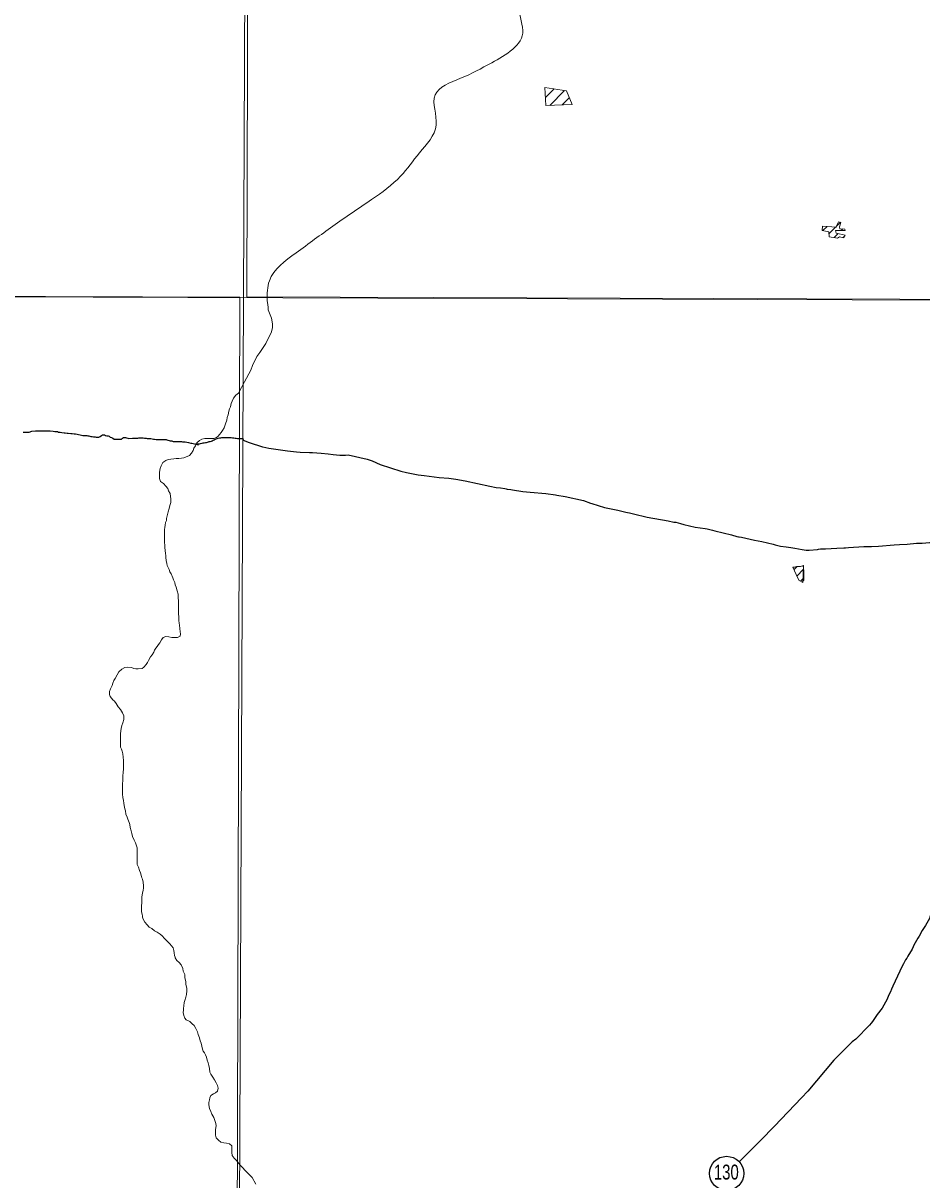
# Model space of a CAD drawing. Extents: x 553962 to 842807, y 8883888 to 9032388.
# Drawn here: x 595557 to 599781, y 8905786 to 8911220 of the extents above; entities that cross this region are included whole.
import ezdxf
from ezdxf.enums import TextEntityAlignment as Align

# ---------------------------------------------------------------- set-up
doc = ezdxf.new("R2010")
doc.units = 0
doc.header["$LTSCALE"] = 200
doc.layers.add('6', color=7, linetype='Continuous', lineweight=13)

msp = doc.modelspace()

# ---------------------------------------------------------------- linework, layer by layer
at = {"layer": '6'}
for p, q in [((598011.9, 8910870), (598052.8, 8910910.9)), ((598032.2, 8910833.7), (598101.8, 8910903.3)), ((598090.8, 8910835.7), (598123.8, 8910868.8)), ((599315.9, 8910245.3), (599335.8, 8910265.2)), ((599343.8, 8910230.8), (599375.6, 8910262.5)), ((599379.9, 8910266.9), (599397.8, 8910284.7)), ((599400.9, 8910245.4), (599408.4, 8910253)), ((599367.8, 8910212.3), (599386.4, 8910230.9)), ((599410.3, 8910212.4), (599419.1, 8910221.2)), ((574653.9, 8910009.3), (626625.7, 8909822.1)), ((599180, 8908652.7), (599194.5, 8908667.1)), ((599192.6, 8908622.8), (599224, 8908654.2)), ((599210.4, 8908598.2), (599221.5, 8908609.3))]:
    msp.add_line(p, q, dxfattribs=at)
at = {"layer": '6', "lineweight": 25}
msp.add_line((596590.3, 8909268.1), (596591.5, 8909261.3), dxfattribs=at)
at = {"layer": '6'}
for points in [[(596655.5, 8924715.8), (596593.3, 8909930.3), (596531.7, 8896026.7)], [(596627.8, 8909589.1), (596635.4, 8909611), (596655.3, 8909654), (596669.8, 8909672.5), (596698.4, 8909714.8), (596724.9, 8909769.1), (596729.8, 8909790.3), (596729.5, 8909807.5), (596724.5, 8909833.3), (596708.7, 8909872.6), (596708.4, 8909884.4), (596706.9, 8909897.8), (596703.8, 8909915.9)], [(596275.7, 8909174.6), (596288.2, 8909175.5), (596301.7, 8909176.9), (596311.7, 8909178.4), (596338.8, 8909188.3), (596347.8, 8909199.7), (596355.9, 8909212.7), (596359.4, 8909222.7), (596366.5, 8909233.7), (596373.6, 8909248.1), (596385.6, 8909259.1), (596397.7, 8909265.5), (596411.7, 8909268.9), (596453.7, 8909268.7), (596465.8, 8909273.5), (596474, 8909279.4), (596480.5, 8909287.6), (596487.5, 8909297.6), (596493.4, 8909307), (596502, 8909319.5), (596508.7, 8909337), (596514, 8909354.6), (596516.7, 8909367), (596520.3, 8909380.5), (596523.9, 8909397), (596527.4, 8909408), (596531, 8909417.9), (596535.1, 8909433.9), (596539.1, 8909443.9), (596545.7, 8909457.9), (596556.2, 8909471.9), (596569.8, 8909481.8), (596597.3, 8909535.3), (596627.8, 8909589.1)], [(596220.8, 8908789.1), (596221, 8908826.6), (596222.1, 8908840.6), (596223.1, 8908851.1), (596225.2, 8908861.6), (596226.2, 8908874.6), (596230.3, 8908884.1), (596230.8, 8908893.6), (596235.4, 8908912.1), (596239, 8908923.6), (596243, 8908940.1), (596246.6, 8908953.6), (596250.7, 8908967.6), (596250.8, 8908984.6), (596249.8, 8908995.6), (596247.4, 8909010.6), (596240.9, 8909023.6), (596237.5, 8909034.2), (596228.5, 8909045.2), (596217.1, 8909056.8), (596203.1, 8909066.9), (596197.7, 8909081.4), (596197.7, 8909093.9), (596198.3, 8909109.9), (596201.9, 8909127.4), (596205.9, 8909140.9), (596214, 8909155.9), (596227.1, 8909164.8), (596238.6, 8909169.8), (596251.6, 8909171.7), (596265.1, 8909172.6), (596275.7, 8909174.6)], [(595978.5, 8908119.2), (595983.6, 8908131.2), (595989.1, 8908141.2), (595998.7, 8908158.2), (596006.8, 8908172.2), (596020.8, 8908184.6), (596035.4, 8908193.5), (596045.9, 8908194), (596065.9, 8908192.4), (596076.9, 8908188.3), (596086.9, 8908186.8), (596097.9, 8908186.7), (596116.5, 8908188.6), (596125, 8908195.1), (596136.1, 8908207.5), (596141.1, 8908216), (596146.2, 8908226.5), (596156.2, 8908242.4), (596163.3, 8908252.9), (596170.8, 8908264.4), (596174.9, 8908274.4), (596180.9, 8908283.3), (596187, 8908291.3), (596194, 8908300.8), (596199.6, 8908309.3), (596207.2, 8908323.2), (596215.2, 8908333.7), (596227.7, 8908339.2), (596241.2, 8908336.6), (596255.7, 8908334.5), (596271.8, 8908333.4), (596283.3, 8908333.4), (596295.1, 8908339.9), (596297.3, 8908350.8), (596295.4, 8908360.8), (596293, 8908375.8), (596291.5, 8908391.9), (596290.6, 8908401.9), (596288.6, 8908413.9), (596288.2, 8908429.9), (596287.8, 8908446.9), (596288, 8908490.5), (596286.6, 8908508), (596286.1, 8908518), (596285.2, 8908537.5), (596281.3, 8908553.1), (596275.8, 8908571.1), (596272.4, 8908582.1), (596269.5, 8908592.7), (596263.5, 8908604.7), (596260, 8908614.2), (596252.6, 8908632.3), (596246.7, 8908642.8), (596243.2, 8908653.3), (596234.8, 8908671.4), (596232.8, 8908681.4), (596229.9, 8908695.4), (596228, 8908709), (596227, 8908719.5), (596226, 8908729), (596225.1, 8908743), (596223.7, 8908756), (596222.7, 8908768.5), (596221.8, 8908778.6), (596220.8, 8908789.1)], [(599174.8, 8908665), (599181.8, 8908664.8), (599191.6, 8908667.3), (599201.1, 8908666.7), (599210.7, 8908667.4), (599224.2, 8908672.1), (599225, 8908672.2), (599220.6, 8908592.6)], [(599220.6, 8908592.6), (599204.7, 8908601.3), (599197.1, 8908612.2), (599174.8, 8908665)], [(599224.2, 8908672.1), (599223.5, 8908670.4), (599225.7, 8908647.6), (599225.6, 8908640.5)], [(599225.6, 8908640.5), (599225.3, 8908603.8), (599222, 8908600), (599219.8, 8908595.6), (599220.6, 8908592.6)], [(596014.3, 8907828.6), (596014.4, 8907881.9), (596016.5, 8907895.9), (596018.1, 8907906.9), (596021.6, 8907919.9), (596026.2, 8907932.8), (596029.8, 8907948.8), (596029.8, 8907966.3), (596024.4, 8907980.4), (596014.5, 8907995), (596004, 8908008), (595994.1, 8908024.1), (595986.1, 8908034.1), (595979.2, 8908041.2), (595966.7, 8908056.8), (595963.3, 8908066.3), (595963.8, 8908080.8), (595967.9, 8908092.8), (595975, 8908108.8), (595978.5, 8908119.2)], [(596049.9, 8907479.9), (596046.2, 8907490.3), (596040.2, 8907503.9), (596038.8, 8907519.4), (596035.3, 8907529.4), (596031.9, 8907545.5), (596030.4, 8907555.5), (596029.5, 8907568.5), (596025.6, 8907582), (596024.6, 8907598.1), (596024.9, 8907649.1), (596025.4, 8907658.6), (596026, 8907674.1), (596026.5, 8907683.6), (596027.6, 8907700.1), (596029.2, 8907716.6), (596029.4, 8907756.2), (596027.9, 8907771.7), (596025, 8907786.7), (596022.6, 8907799.7), (596019.1, 8907808.8), (596014.2, 8907819.3), (596014.3, 8907828.6)], [(596115.7, 8907204.3), (596113.9, 8907210.7), (596108, 8907227.8), (596104.5, 8907239.3), (596099.1, 8907254.8), (596093.7, 8907267.4), (596092.7, 8907279.4), (596093, 8907346), (596090.6, 8907355.5), (596085.1, 8907369.5), (596078.2, 8907382.1), (596070.8, 8907398.6), (596067.8, 8907413.7), (596065.4, 8907425.2), (596059.4, 8907441.7), (596058, 8907454.7), (596055, 8907464.3), (596049.9, 8907479.9)], [(596117.5, 8907024.2), (596116.1, 8907034), (596114.2, 8907044.6), (596114.5, 8907115.1), (596118.1, 8907133.1), (596120.6, 8907146.6), (596123.2, 8907157.1), (596123.2, 8907168.1), (596121.3, 8907184.2), (596117.4, 8907198.2), (596115.7, 8907204.3)], [(596271.3, 8906832.7), (596268.8, 8906840.6), (596267.4, 8906852.6), (596266, 8906863.6), (596262.5, 8906875.6), (596254.5, 8906886.2), (596246.1, 8906895.2), (596235.1, 8906906.3), (596222.2, 8906920.4), (596211.2, 8906932.4), (596201.2, 8906941), (596187.3, 8906949.1), (596175.3, 8906955.7), (596161.8, 8906966.2), (596149.8, 8906973.8), (596139.9, 8906984.4), (596128.4, 8906996.9), (596121.5, 8907010), (596118, 8907020.5), (596117.5, 8907024.2)], [(596279.7, 8906817), (596272.3, 8906829.5), (596271.3, 8906832.7)], [(596461.2, 8906005.4), (596461.2, 8906022.7), (596463.8, 8906039.2), (596463.4, 8906051.2), (596457.4, 8906065.3), (596453.5, 8906078.3), (596444.6, 8906095.4), (596439.1, 8906106.9), (596433.7, 8906120.9), (596429.8, 8906138.5), (596429.8, 8906149), (596432.9, 8906162), (596433.9, 8906171.5), (596439.5, 8906182), (596451, 8906189.9), (596461, 8906195.4), (596470.1, 8906202.3), (596474.2, 8906216.8), (596471.2, 8906229.4), (596464.2, 8906241.4), (596455.8, 8906256), (596447.9, 8906268), (596439.9, 8906282.6), (596434.5, 8906292.6), (596433, 8906308.7), (596429.1, 8906323.7), (596426.2, 8906335.2), (596422.7, 8906348.8), (596419.3, 8906361.8), (596413.8, 8906373.3), (596408.8, 8906382.4), (596403.4, 8906390.9), (596399.9, 8906400.4), (596397, 8906413.4), (596393.6, 8906429), (596389.6, 8906440), (596386.2, 8906452.6), (596379.7, 8906468.6), (596376.3, 8906481.6), (596368.8, 8906497.2), (596361.4, 8906511.2), (596351.4, 8906519.3), (596340, 8906529.4), (596324, 8906537.5), (596317.3, 8906546.3), (596312.9, 8906557.6), (596309.7, 8906572.8), (596311, 8906582.9), (596310.7, 8906590.6), (596312.8, 8906603.1), (596313.4, 8906618.6), (596316.9, 8906629.1), (596321.5, 8906645.1), (596325.6, 8906657.6), (596326.1, 8906673.6), (596325.7, 8906686.1), (596321.8, 8906703.6), (596321.3, 8906715.7), (596317.4, 8906737.2), (596316.5, 8906750.7), (596310, 8906765.8), (596307.1, 8906779.8), (596300.2, 8906796.3), (596291.2, 8906807.9), (596279.7, 8906817)], [(596650.2, 8905765.8), (596633.6, 8905797.4), (596611.2, 8905818.6), (596577.4, 8905855.5), (596559.7, 8905877.5), (596548.7, 8905888.6), (596540.2, 8905900.2), (596538.3, 8905914.2), (596537.9, 8905930.7), (596537.5, 8905945.2), (596527, 8905955.3), (596513.5, 8905957.9), (596500.5, 8905959.4), (596487, 8905962.5), (596476, 8905972.6), (596464.6, 8905983.1), (596461.1, 8905995.7), (596461.2, 8906005.4)]]:
    msp.add_lwpolyline(points, dxfattribs=at)
for points in [[(607600.8, 8920952.4), (596639.8, 8920989.8), (596608.8, 8909934.4), (607569.8, 8909894.9)], [(598009.1, 8910917.7), (598014.1, 8910833.1), (598136.5, 8910837.3), (598110.5, 8910902)], [(599378.7, 8910262.3), (599314.2, 8910266.7), (599311.8, 8910246.2), (599342.8, 8910239.1), (599345.6, 8910215.6), (599383.5, 8910210), (599394.2, 8910216.7), (599414.6, 8910211.2), (599420, 8910223.3), (599378.4, 8910232.8), (599374.7, 8910245.7), (599420.2, 8910245.3), (599418.8, 8910252.9), (599394.5, 8910253.1), (599393.8, 8910262.9), (599400.1, 8910284.1), (599388, 8910287.2), (599381, 8910270.6)], [(596575.8, 8909932.4), (585614.8, 8909969.8), (585583.8, 8898914.4), (596544.8, 8898874.9)]]:
    msp.add_lwpolyline(points, close=True, dxfattribs=at)
at = {"layer": '6', "lineweight": 25}
for points in [[(595557.4, 8909298.7), (595561.5, 8909298.4), (595565.6, 8909298.4), (595574.5, 8909297.8), (595579.1, 8909297.8), (595585.6, 8909297.8), (595597.6, 8909303.7)], [(595597.6, 8909303.7), (595615.6, 8909305.1), (595622.6, 8909305), (595627.6, 8909305), (595639.1, 8909304.9), (595644.1, 8909304.9), (595655.6, 8909304.8), (595662.1, 8909304.8), (595676.6, 8909304.7), (595683.6, 8909304.6), (595697.6, 8909303), (595705.6, 8909302), (595718.6, 8909300.9), (595723.1, 8909299.3), (595731.1, 8909298.3), (595739.6, 8909297.2), (595750.1, 8909295.7), (595754.6, 8909295.1), (595764.1, 8909294.6), (595769.1, 8909294), (595781.6, 8909293), (595787.1, 8909292.4), (595797.6, 8909290.8), (595802.6, 8909290.3), (595811.1, 8909289.3), (595817.6, 8909287.2), (595824.6, 8909285.7), (595831.1, 8909284.1), (595838.1, 8909283.6), (595844.6, 8909283.5), (595850.1, 8909283), (595856.1, 8909282.9), (595860.6, 8909281.9), (595866.1, 8909281.4), (595871, 8909280.3), (595876, 8909278.8), (595881.5, 8909277.8), (595888.5, 8909276.7), (595895, 8909276.2), (595900.5, 8909275.7), (595907.5, 8909275.6), (595913, 8909275.6), (595919.1, 8909278.5), (595925.6, 8909282.5), (595929.6, 8909285.5), (595933.6, 8909285.9), (595939.6, 8909285.9), (595944.6, 8909283.4), (595951.1, 8909281.8), (595957.1, 8909280.8), (595962.1, 8909279.2), (595966.5, 8909274.7), (595972.5, 8909274.2), (595978.5, 8909271.1), (595985.5, 8909266.1), (595990.5, 8909266), (595998.5, 8909265), (596002.5, 8909265), (596008, 8909264.9), (596012, 8909264.9), (596016, 8909264.9), (596020, 8909265.8), (596024, 8909269.8), (596028.6, 8909272.8), (596032.6, 8909273.8), (596038.6, 8909273.7), (596054.5, 8909269.1)], [(596054.5, 8909269.1), (596070.6, 8909270.5), (596075.6, 8909270.5), (596081.1, 8909270.4), (596085.1, 8909270.4), (596096.1, 8909270.8), (596101.6, 8909271.8), (596111.1, 8909272.2), (596117.6, 8909272.2), (596121.6, 8909272.2), (596127.1, 8909271.1), (596135.1, 8909269.6), (596139.6, 8909269.1), (596146.1, 8909269), (596152.1, 8909269), (596156.6, 8909268.4), (596163.6, 8909267.4), (596169.1, 8909266.4), (596174.6, 8909265.3), (596181.6, 8909264.8), (596187.6, 8909264.7), (596193.1, 8909264.2), (596200.1, 8909264.2), (596206.6, 8909264.1), (596212.1, 8909264.1), (596218.6, 8909264), (596224.1, 8909264), (596228.6, 8909263.5), (596233.1, 8909262.4), (596237.6, 8909260.9), (596244, 8909258.8), (596248.5, 8909258.3), (596255.5, 8909257.3), (596262.5, 8909255.2), (596268, 8909254.7), (596273.5, 8909254.7), (596279.5, 8909254.6), (596287.5, 8909254.6), (596292, 8909254), (596301.5, 8909254), (596306.5, 8909253.4), (596312.5, 8909253.4), (596318.5, 8909253.3), (596334, 8909249.2)], [(596381.5, 8909239.4), (596369, 8909243.5), (596375, 8909243.5), (596379, 8909243.4), (596386, 8909244.4), (596390.5, 8909245.9), (596398.5, 8909246.8), (596402.5, 8909247.8), (596407.5, 8909248.3), (596413.6, 8909249.7), (596418.6, 8909250.7), (596423.6, 8909252.2), (596427.6, 8909253.1), (596431.6, 8909254.1), (596435.6, 8909255.1), (596441.6, 8909257), (596445.6, 8909258), (596449.7, 8909261), (596455.2, 8909263), (596459.7, 8909266.4), (596463.7, 8909267.4), (596469.2, 8909269.4), (596473.2, 8909270.4), (596479.2, 8909271.3), (596485.8, 8909271.8), (596490.8, 8909272.7), (596497.8, 8909274.2), (596501.8, 8909274.2), (596507.3, 8909274.1), (596511.3, 8909274.1), (596515.3, 8909274.1), (596519.3, 8909274.1), (596524.3, 8909274), (596528.3, 8909274), (596534.8, 8909273.9), (596541.3, 8909272.4), (596547.8, 8909271.4), (596553.3, 8909270.3), (596558.3, 8909269.8), (596564.3, 8909268.2), (596568.3, 8909268.2), (596574.3, 8909268.2), (596580.3, 8909268.1), (596585.8, 8909268.1), (596590.3, 8909268.1)], [(596591.5, 8909261.3), (596619.6, 8909249.8), (596682.6, 8909229.6), (596683.9, 8909229.3)], [(596334, 8909249.2), (596344.5, 8909247.2), (596349.5, 8909246.1), (596356, 8909245.6), (596381.5, 8909239.4)], [(596683.9, 8909229.3), (596711.5, 8909223.7), (596744.5, 8909219.2), (596799.3, 8909210.1), (596842.1, 8909206.1)], [(596842.1, 8909206.1), (596858.3, 8909204.6), (596902.4, 8909203.4)], [(596902.4, 8909203.4), (596917, 8909203.1), (596957.6, 8909199.9)], [(596957.6, 8909199.9), (596990.5, 8909197.3), (597014.2, 8909192.9), (597045.7, 8909189.7), (597072.2, 8909191.1)], [(597072.2, 8909191.1), (597084.7, 8909191.8), (597174.5, 8909170.9), (597197.8, 8909163.1), (597234.6, 8909146.1), (597332.2, 8909115.9), (597359.4, 8909109.1), (597359.4, 8909109.1)], [(597359.4, 8909109.1), (597413.5, 8909097.8), (597441.7, 8909094.5)], [(597441.7, 8909094.5), (597513, 8909085.9), (597557.5, 8909082.1), (597590.5, 8909077.7), (597634.7, 8909070.3), (597750.9, 8909045), (597780.8, 8909039.3), (597800, 8909036.6)], [(597800, 8909036.6), (597820.6, 8909033.7), (597826.4, 8909032.4)], [(597826.4, 8909032.4), (597831.3, 8909031.2), (597848.5, 8909029.3), (597857.5, 8909027.9)], [(597857.5, 8909027.9), (597905.8, 8909020.3), (597940, 8909016.9)], [(597940, 8909016.9), (598013.1, 8909009.7), (598058.4, 8909004.1), (598065, 8909003)], [(598065, 8909003), (598103.6, 8908996.2), (598190.4, 8908976.9), (598223.4, 8908965.7), (598229, 8908963.9)], [(598229, 8908963.9), (598288.9, 8908945.4), (598352.3, 8908932.1), (598389.3, 8908922.7), (598397.9, 8908921.9), (598406.4, 8908919.8), (598424.8, 8908915.4)], [(598424.8, 8908915.4), (598490.2, 8908899.6), (598588.7, 8908882.5), (598615.2, 8908875.7), (598623.3, 8908875.6)], [(598623.3, 8908875.6), (598624.2, 8908875.5), (598646.7, 8908868.9)], [(598646.7, 8908868.9), (598662.4, 8908864.2), (598715.2, 8908852.1), (598762.3, 8908845.3)], [(598762.3, 8908845.3), (598771.7, 8908843.9), (598796.6, 8908838.7), (598807.5, 8908834.7), (598885.4, 8908816.6), (598910.8, 8908808.4), (598918.4, 8908807.2), (598921.5, 8908806.8)], [(598921.5, 8908806.8), (598932.8, 8908805), (598993.5, 8908790.9), (599029.2, 8908784.9), (599055.3, 8908778.1), (599081.1, 8908772.6), (599091.1, 8908769.1), (599116.3, 8908762.8), (599142.3, 8908760.2), (599164.2, 8908757)], [(599436, 8908756), (599508, 8908760.8), (599543.3, 8908760.8), (599576.3, 8908762.6), (599650.4, 8908769.1)], [(599650.4, 8908769.1), (599675.7, 8908771.4), (599711.8, 8908772.9), (599755.5, 8908776.9), (599782.2, 8908777), (599816.2, 8908780.5), (599821.1, 8908780.9)], [(599164.2, 8908757), (599183.5, 8908754.2), (599218.5, 8908746.9), (599236.9, 8908744.1), (599250.4, 8908744.1)], [(599250.4, 8908744.1), (599289.5, 8908747.6), (599295, 8908748.4), (599304, 8908749.8)], [(599304, 8908749.8), (599306.6, 8908750.2), (599327.2, 8908750.6), (599380.2, 8908754.2), (599414, 8908754.8)], [(599414, 8908754.8), (599421.4, 8908755), (599436, 8908756)], [(599824.6, 8907040.2), (599816, 8907013.5), (599797.5, 8906981.8), (599781.8, 8906957.7), (599767.9, 8906931.3), (599761.3, 8906921.4), (599743.5, 8906888.8), (599740, 8906881)], [(599740, 8906881), (599735.2, 8906870), (599714.3, 8906836.7), (599709.7, 8906827.8), (599704, 8906819.8), (599694.2, 8906801.6)], [(599694.2, 8906801.6), (599687.8, 8906789.5), (599643.8, 8906695.8), (599638.2, 8906682.4)], [(599638.2, 8906682.4), (599632.7, 8906669.2), (599624.4, 8906652.8), (599617.6, 8906635.6), (599593.6, 8906593), (599571.2, 8906562.6), (599548.8, 8906529.6), (599542.6, 8906522.3)], [(599542.6, 8906522.3), (599534.8, 8906512.8), (599510.6, 8906490.1), (599493.4, 8906470.8), (599469.6, 8906447.3), (599452.6, 8906434.6), (599367, 8906347.8), (599244.3, 8906202), (599214.8, 8906171.2), (599087.5, 8906038.9), (599087.3, 8906038.8)], [(599087.3, 8906038.8), (599022.5, 8905971.3), (598969.8, 8905918.7), (598925.3, 8905874.1)]]:
    msp.add_lwpolyline(points, dxfattribs=at)
msp.add_circle((598863.1, 8905816.4), 80.3, dxfattribs=at)
at = {"layer": '6'}
msp.add_spline([(596703.8, 8909915.9), (596714.2, 8910009.9), (596839.6, 8910140.6), (597012.1, 8910266), (597195, 8910391.4), (597330.8, 8910501.1), (597419.6, 8910610.8), (597498, 8910741.4), (597492.8, 8910882.5), (597613, 8910960.9), (597759.2, 8911034), (597905.6, 8911185.6), (597895.1, 8911300.5), (597968.2, 8911373.7), (597957.8, 8911425.9), (597853.3, 8911509.5), (597801.1, 8911598.3), (597889.9, 8911729), (598031, 8911870), (598140.7, 8911786.4), (598271.3, 8911875.3), (598354.9, 8911995.4), (598297.4, 8912120.8), (598459.4, 8912178.3), (598694.5, 8912204.4), (598882.6, 8912209.7), (599112.5, 8912314.2), (599201.4, 8912340.3), (599285, 8912455.2), (599384.2, 8912502.3), (599426, 8912612.4), (599520.1, 8912769.3), (599645.5, 8912873.8), (599650.7, 8912967.9), (599603.7, 8913082.9), (599520.1, 8913229.3), (599285, 8913417.5)], degree=3, dxfattribs=at)

# ---------------------------------------------------------------- texts
at = {"layer": '6', "width": 0.75}
msp.add_text('130', height=70, dxfattribs=at).set_placement((598861.6, 8905787.7), align=Align.CENTER)

doc.saveas('drawing.dxf')
